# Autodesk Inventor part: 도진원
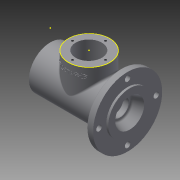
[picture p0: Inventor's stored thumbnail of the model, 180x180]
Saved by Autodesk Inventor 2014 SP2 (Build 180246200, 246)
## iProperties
Created: 2016-08
Part Number: 도진원
Material: Generic
Document SubType Name: Modeling
Designer: 달님반
Density: 1 g/cm^3
Appearance: Default
Author: 달님반
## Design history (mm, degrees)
sketch "스케치1"
  geometry: L1 (0, 0)-(115, 0); L2 (0, 21)-(0, 31); L3 (0, 31)-(102, 31); L4 (102, 31)-(102, 50); L5 (102, 50)-(112, 50); L6 (112, 50)-(112, 31); L7 (112, 31)-(115, 31); L8 (115, 31)-(115, 21); L9 (115, 21)-(102.991, 16.711); L10 (87.3, 16.5)-(86, 16.5); L11 (86, 16.5)-(86, 17.2); L12 (85.7, 17.5)-(26, 17.5); L13 (26, 17.5)-(26, 18.5); L14 (26, 18.5)-(24.25, 18.5); L15 (24.25, 18.5)-(24.25, 17.5); L16 (24.25, 17.5)-(21, 17.5); L17 (21, 17.5)-(21, 20); L18 (21, 20)-(12, 20); L19 (12, 20)-(12, 24); L20 (12, 24)-(9, 24); L21 (9, 24)-(9, 21); L22 (9, 21)-(0, 21); L23 (101, 13.886)-(101, 12.75); L24 (90.3, 13.5)-(90.3, 10); L25 (90.3, 10)-(93, 10); L26 (93, 10)-(93, 12.2); L27 (93.3, 12.5)-(100.3, 12.5); L28 (101, 12.75)-(100.3, 12.5); A1 r 0.3 centre (93.3, 12.2) between (93.3, 12.5) and (93, 12.2); A2 r 0.3 centre (85.7, 17.2) between (86, 17.2) and (85.7, 17.5); A3 r 3 centre (87.3, 13.5) between (90.3, 13.5) and (87.3, 16.5); A4 r 3 centre (104, 13.886) between (102.991, 16.711) and (101, 13.886); 4 further points
  constraints: 56 end point, 15 parallel, 8 perpendicular, 8 point on circle, 8 point on line, 8 tangent, 4 centre point, 2 collinear, 2 vertical alignment, 1 horizontal
  dimensions: "d19" = 3 distance of L19.end L20.end; "d20" = 21 distance between parallel lines of L17 L2; "d21" = 1.75 distance of L13.end L14.end; "d23" = 26 distance between parallel lines of L13 L2; "d26" = 3 distance of L6.end L7.end; "d27" = 13 distance between parallel lines of L8 L4; "d28" = 14 distance from line of point (101, 16) L8; "d30" = 115 distance between parallel lines of L8 L2; "d31" = 35 diameter of L12 L1; "d32" = 37 diameter of L14 L1; "d33" = 35 diameter of L16 L1; "d34" = 40 diameter of L18 L1; "d35" = 48 diameter of L20 L1; "d36" = 42 diameter of L22 L1; "d37" = 62 diameter of L3 L1; "d38" = 33 diameter of L10 L1; "d40" = 20 diameter of L25 L1; "d41" = 25 diameter of L27 L1; "d42" = 2.7 distance of L24.end L25.end; "d43" = 7.3 distance of point (93, 12.5) L27.end; "d45" = 60 distance of point (86, 17.5) L12.end; "d46" = 0.7 horizontal distance of L23.end L27.end; "d47" = 0.3 radius of A1; "d48" = 32 diameter of point (101, 16) L1; "d49" = 42 diameter of L8.end L1; "d50" = 62 diameter of L7 L1; "d51" = 100 diameter of L5 L1; "d53" = 0.3 radius of A2; "d54" = 3 radius of A3; "d90" = 12 distance between parallel lines of L19 L2; "d91" = 3 radius of A4
revolve "회전1" sketch "스케치1" stored, may be unused: angle "d52" = 90 deg
node "작업 평면1"
sketch "스케치2"
  geometry: L1 (0, -31)-(0, 31) reference; C1 r 30 at (56, 0); 1 further point
  constraints: 1 centre point
  dimensions: "d56" = 60 diameter of C1; "d57" = 56 distance from line of C1.centre L1
extrude "돌출1" join sketch "스케치2" stored distance "d58" = 10; taper "d59" = 0 deg
sketch "스케치3"
  geometry: C1 r 30 at (0, 0) reference; 1 further point
sketch "스케치4"
  geometry: L1 (0, -31)-(-102, -31) reference; L2 (-122.4, 49)-(20.4, 49) reference; L3 (-55.721, 49)-(-36.721, 49); L4 (-36.721, 49)-(-36.721, -23); L5 (-36.721, -23)-(-55.721, -23); L6 (-55.721, -23)-(-55.721, 49); 1 further point
  constraints: 8 end point, 2 parallel, 1 horizontal, 1 perpendicular, 1 point on line
  dimensions: "d62" = 38 diameter of L4 L6; "d89" = 8 distance between parallel lines of L1 L5
revolve "회전2" sketch "스케치4" stored, may be unused: angle "d63" = 90 deg
sketch "스케치5" dims "d64" = 48
  geometry: C1 r 30 at (0, 0) reference; 3 further points
  constraints: 1 coincident, 1 vertical alignment, 2 other
hole "구멍1" sketch "스케치5" at (0, 24) diameter "d65" = 3.242; stored, may be unused: countersink angle "d69" = 90 deg, drill point angle "d71" = 118 deg; dims "d66" = 8, "d67" = 4, "d68" = 2, "d70" = 10
sketch "스케치6" dims "d75" = 83
  geometry: C1 r 50 at (0, 0) reference; C2 r 4 at (-41.5, 0); 1 further point
  constraints: 1 centre point, 1 coincident, 1 horizontal alignment, 2 other
  dimensions: "d76" = 8 diameter of C2
extrude "돌출2" cut sketch "스케치6" distance "d77" = 10; taper "d78" = 0 deg
fillet "모깎기1" dims "d82" = 3
fillet "모깎기2" dims "d83" = 3
sketch "스케치7"
  geometry: 1 further point
node "작업 평면2"
sketch "스케치8"
  geometry: L1 (-75.714, 42.388)-(-36.828, 42.388); L2 (-36.828, 42.388)-(-36.828, 32.322); L3 (-36.828, 32.322)-(-75.714, 32.322); L4 (-75.714, 32.322)-(-75.714, 42.388); 2 further points
  constraints: 1 midpoint, 2 other
feature "엠보싱1" sketch "스케치8" dims "d85" = 0.5, "d86" = 0
feature "스레드1" dims "d87" = 10, "d88" = 0
node "솔리드1"
pattern_circular "원형 패턴1" dims angle "d73" = 360 deg
pattern_circular "원형 패턴2" dims angle "d80" = 360 deg
other parameters: "d55" = 49
